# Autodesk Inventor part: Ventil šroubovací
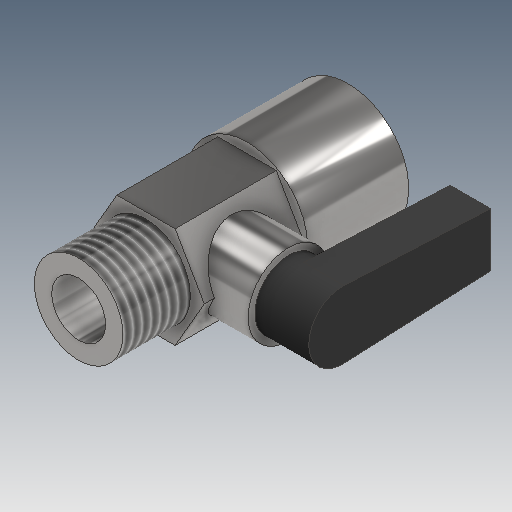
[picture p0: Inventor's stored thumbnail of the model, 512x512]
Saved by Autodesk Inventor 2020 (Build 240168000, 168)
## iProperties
Created: 2025-03
Part Number: Ventil šroubovací
Material: Ocel
Document SubType Name: Modeling
Designer: doma
Density: 7.85 g/cm^3
Appearance: Ocel – leštěná
Mass: 60.7983 g
Surface Area: 46.0852 cm^2
Volume: 7.74501 cm^3
Author: doma
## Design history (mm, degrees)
sketch "Náčrt1"
  geometry: L1 (4.33, 7.5)-(8.66, 0); L2 (8.66, 0)-(4.33, -7.5); L3 (4.33, -7.5)-(-4.33, -7.5); L4 (-4.33, -7.5)-(-8.66, 0); L5 (-8.66, 0)-(-4.33, 7.5); L6 (-4.33, 7.5)-(4.33, 7.5); 2 further points
  constraints: 12 end point, 1 coincident, 13 other
  dimensions: "d0" = 15 distance between parallel lines of L3 L6
extrude "Vysunutí1" new body sketch "Náčrt1" distance "d1" = 15; taper "d2" = 0 deg
sketch "Náčrt2"
  geometry: C1 r 6.578 at (0, 0); 1 further point
  constraints: 1 centre point, 1 coincident
  dimensions: "d3" = 13.157 diameter of C1
extrude "Vysunutí2" join sketch "Náčrt2" distance "d4" = 10; taper "d5" = 0 deg
sketch "Náčrt3"
  geometry: C1 r 9 at (0, 0); 1 further point
  constraints: 1 centre point, 1 coincident
  dimensions: "d6" = 18 diameter of C1
extrude "Vysunutí3" join sketch "Náčrt3" distance "d7" = 15; taper "d8" = 0 deg
sketch "Náčrt4"
  geometry: C1 r 4 at (0, 0); 1 further point
  constraints: 1 centre point, 1 coincident
  dimensions: "d9" = 8 diameter of C1
extrude "Vysunutí4" cut sketch "Náčrt4" extent not by distance; stored distance "d10" = 0; taper "d11" = 0 deg
sketch "Náčrt5"
  geometry: 2 further points
hole "Díra1" sketch "Náčrt5" at (0, 0) diameter "d12" = 11.445; stored, may be unused: countersink angle "d16" = 90 deg, drill point angle "d18" = 118 deg; dims "d13" = 8, "d14" = 4, "d15" = 2, "d17" = 12
feature "Závit1" dims "d19" = 18, "d20" = 0
node "Pracovní rovina1"
sketch "Náčrt6"
  geometry: L1 (0, -15)-(0, 0) reference; C1 r 6 at (0, -7.5)
  constraints: 1 centre point, 1 midpoint
  dimensions: "d21" = 12 diameter of C1
extrude "Vysunutí5" join sketch "Náčrt6" stored distance "d22" = 15; taper "d23" = 0 deg
extrude "Vysunutí6" join sketch "Náčrt6" distance "d24" = 5; taper "d25" = 0 deg
sketch "Náčrt7"
  geometry: L1 (7.5, 0)-(-7.5, 0) reference; C1 r 5 at (0, 0)
  constraints: 1 centre point, 1 midpoint
  dimensions: "d26" = 10 diameter of C1
extrude "Vysunutí7" join sketch "Náčrt7" distance "d27" = 8; taper "d28" = 0 deg
sketch "Náčrt9"
  geometry: L1 (0.228, 4.995)-(22, 4); L2 (22, 4)-(22, -4); L3 (22, -4)-(0.228, -4.995); L4 (7.5, 0)-(7.5, 7.5) reference; L5 (0, 0)-(7.5, 0); A1 r 5 centre (0, 0) between (0.228, 4.995) and (0.228, -4.995) reference
  constraints: 8 end point, 2 point on circle, 2 tangent, 1 horizontal, 1 vertical, 1 other
  dimensions: "d34" = 8 distance of L1.end L2.end; "d35" = 22 distance from line of L2 L5.start
extrude "Vysunutí9" join sketch "Náčrt9" distance "d36" = 6; taper "d37" = 0 deg
node "Těleso1"
